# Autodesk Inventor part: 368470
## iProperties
Created: 2006-08
Part Number: 368470
Material: Ms
Description: Scheibe
Vendor: Autodesk Inc.
Document SubType Name: Modeling
Standard: DIN 125
Designer: I.Baliuc
Standards Organization: DIN
Language: de-DE
Size Designation: A 10.5
Categories: <MemberInstance Version="R10.0.0"><Categories><Category DisplayName="Schrauben" InternalName="e4da775c-781d-43d5-af7c-5136215cf5a6" Mnemonic="FSTN"><Category Di
Density: 8.47 g/cm^3
Mass: 3.85502 g
Surface Area: 6.46775 cm^2
Volume: 0.455138 cm^3
Abmessung: A 10
Author: T.Messerschmitt
Comments: DIN 125 - A 10.5
Revision Number: 368470
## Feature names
1. Körper [Extrusion]
